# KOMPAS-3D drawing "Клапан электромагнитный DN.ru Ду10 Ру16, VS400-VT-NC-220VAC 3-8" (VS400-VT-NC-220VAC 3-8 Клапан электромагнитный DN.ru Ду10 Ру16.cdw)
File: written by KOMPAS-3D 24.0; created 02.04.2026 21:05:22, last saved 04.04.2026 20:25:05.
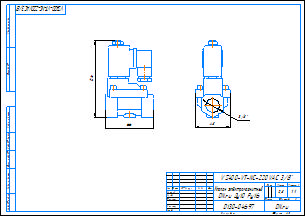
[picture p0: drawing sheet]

Document properties: c3d_UniqueCompID: ef56311e-7521-43dc-8291-0e6108b3d81d; Обозначение: VS400-ET-NC-220VAC 3-8; Наименование: Клапан электромагнитный DN.ru Ду10 Ру16; Автор: artio; Класс точности: c; Знак неуказанной шероховатости: Шероховатость не задана; Рассекать на разрезах: Да; Автор: artio; Форматы листов документа: A3; Полное имя файла: VS400-VT-NC-220VAC 3-8 Клапан электромагнитный DN.ru Ду10 Ру16.m3d; Масса: 0.797; Наименование: Клапан электромагнитный DN.ru Ду10 Ру16; Количество листов документа: 1; Примечание: D130-04697

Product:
- Body: Тело 1  | qty 1
    Масса: 1.030062
- Part/product: Клапан электромагнитный DN.ru Ду10 Ру16  | designation VS400-VT-NC-220VAC 3-8
    Масса: 0.797
    Раздел спецификации: Прочие изделия
    Примечание: D130-04697
    additional columns: ef56311e-7521-43dc-8291-0e6108b3d81d; VS400-ET-NC-220VAC 3-8; artio; c; Шероховатость не задана; Да

Views: Вид 1, Спереди, Проекционный вид 2
Referenced files in C:\Users\artio\OneDrive\Рабочий стол\Клапан электромагнитный DN.ru VS4x-xT-NC-x\DN10\: VS400-ET-NC-220VAC 3-8 Клапан электромагнитный DN.ru Ду10 Ру16.m3d
Referenced files in C:\Users\artio\OneDrive\Рабочий стол\Клапан электромагнитный DN.ru\VS400-VT-NC\VS400-VT-NC-220VAC\: VS400-VT-NC-220VAC 3-8 Клапан электромагнитный DN.ru Ду10 Ру16.m3d, VS400-VT-NC-220VAC 3-8 Клапан электромагнитный DN.ru Ду10 Ру16.cdw
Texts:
  VS400-VT-NC-220VAC 3-8
  Линейный размер
  Клапан электромагнитный
  DN.ru Ду10 Ру16
  VS400-VT-NC-220VAC 3/8"
  VS400-VT-NC-220VAC 3/8"-
  Клапан электромагнитный DN.ru Ду10 Ру16
  VS400-VT-NC-220VAC 3-8 Клапан электромагнитный DN.ru Ду10 Ру16
Dimensions and other numbers on the sheet: 0; 3; 2; 4; 48; 3/8"; 66; 106; 1:1; 1; 0,8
